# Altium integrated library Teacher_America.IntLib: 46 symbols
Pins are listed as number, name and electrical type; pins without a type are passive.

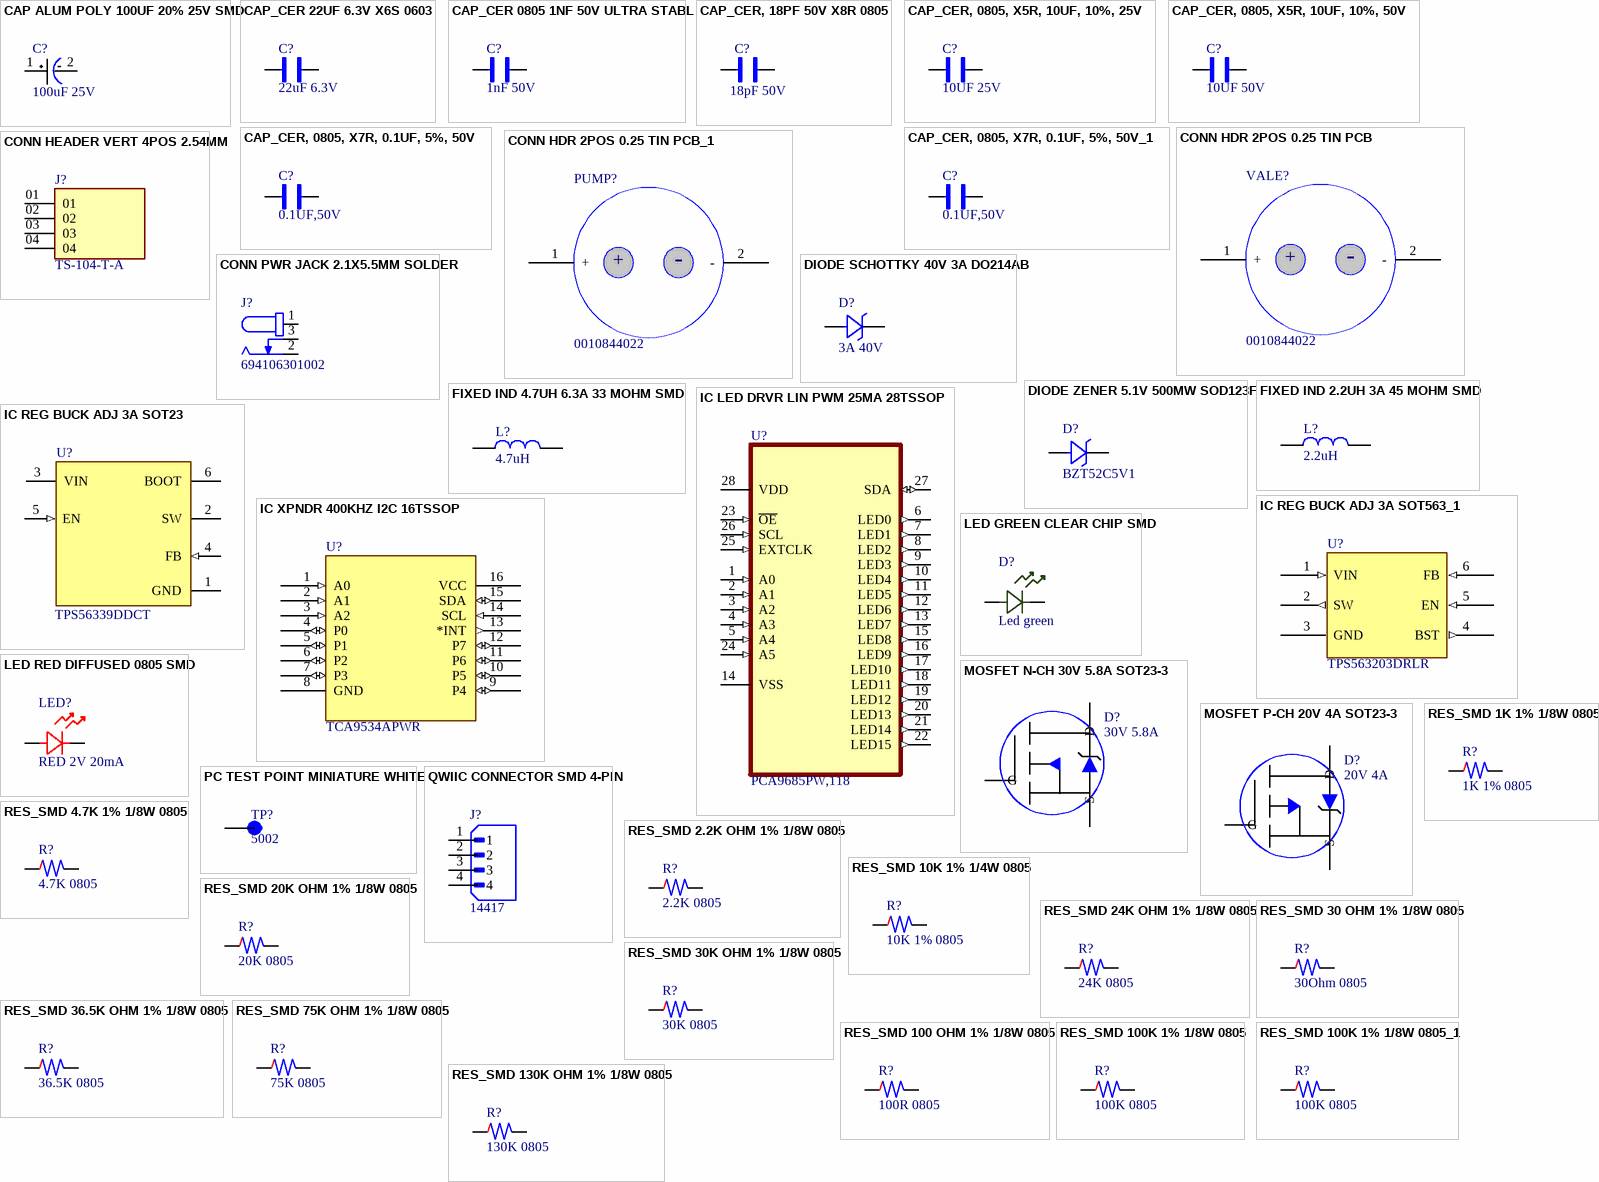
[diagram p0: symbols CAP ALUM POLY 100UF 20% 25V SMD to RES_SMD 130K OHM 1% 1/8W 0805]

## CAP ALUM POLY 100UF 20% 25V SMD
designator C?, comment 100uF 25V
WCAP-PSLC Aluminum Polymer Capacitors; Manufacturer: Wurth Elektronik; Manufacturer Part Number: 875075561005; Manufacturer Lifecycle Status: ACTIVE; Capacitance: 100µF; ESR (Equivalent Series Resistance): 15mΩ; Leakage Current: 500µA; Life (Hours): 2000hours; Pitch: 10.3mm; Polarity: Polar; Ripple Current: 4.8A; Tolerance: 20%; YEOL: 1 = Estimated lifetime > 10 years; LIB MADE BY: MR HOANG
footprint CAP_ALUM_SMD_D10_H12.4
pins: 1, 2

## CAP_CER 22UF 6.3V X6S 0603
designator C?, comment 22uF 6.3V
6.3V 22uF X6S ±20% 0603 Multilayer Ceramic Capacitors MLCC - SMD/SMT ROHS; Manufacturer: Murata; Manufacturer Part Number: GRM188C80J226ME15D; Manufacturer Lifecycle Status: IN PRODUCTION; Capacitance: 22µF; LIB MADE BY: MR HOANG
footprint CAP_CER_0603
pins: 1, 2

## CAP_CER 0805 1NF 50V ULTRA STABL
designator C?, comment 1nF 50V
Cap Ceramic 0.001uF 50V X8R 10% Pad SMD 0805 150C T/R Automotive AEC-Q200; Manufacturer: Yageo Group; Manufacturer Part Number: C0805C102K5HACAUTO; Temperature Coefficient: 30ppm/°C; LIB MADE BY: MR HOANG
footprint CAP_CER_0805
pins: 1, 2

## CAP_CER, 18PF 50V X8R 0805
designator C?, comment 18pF 50V
Multilayer Ceramic Capacitors MLCC - SMD/SMT 50V 18pF X8R 0805 5%; Manufacturer: Yageo Group; Manufacturer Part Number: C0805C180J5HACTU; Temperature Coefficient: 30ppm/°C; LIB MADE BY: MR HOANG
footprint CAP_CER_0805
pins: 1, 2

## CAP_CER, 0805, X5R, 10UF, 10%, 25V
designator C?, comment 10UF 25V
Cap SMD, 0805, X5R, 10UF, 10%, 25V; Manufacturer: Nextgen; Manufacturer Part Number: 0805W106K250CC; LIB MADE BY: MR HOANG
footprint CAP_CER_0805
pins: 1, 2

## CAP_CER, 0805, X5R, 10UF, 10%, 50V
designator C?, comment 10UF 50V
CAP_CER,0805,X5R,10UF,10%,50V; Manufacturer: Nextgen; Manufacturer Part Number: 0805W106K500CC; LIB MADE BY: MR HOANG
footprint CAP_CER_0805
pins: 1, 2

## CAP_CER, 0805, X7R, 0.1UF, 5%, 50V
designator C?, comment 0.1UF,50V
Ceramic Capacitor, Multilayer, Ceramic, 50V, 10% +Tol, 10% -Tol, X7R, 15% TC, 0.1uF, Surface Mount, 0805; Manufacturer: Nextgen; Manufacturer Part Number: 0805B104K500BD; Capacitance: 100nF; LIB MADE BY: MR HOANG
footprint CAP_CER_0805
pins: 1, 2

## CAP_CER, 0805, X7R, 0.1UF, 5%, 50V_1
designator C?, comment 0.1UF,50V
Ceramic Capacitor, Multilayer, Ceramic, 50V, 10% +Tol, 10% -Tol, X7R, 15% TC, 0.1uF, Surface Mount, 0805; Manufacturer: Nextgen; Manufacturer Part Number: 0805B104K500BD; Capacitance: 100nF; LIB MADE BY: MR HOANG
footprint CAP_CER_0805
pins: 1, 2

## CONN HDR 2POS 0.25 TIN PCB
designator VALE?, comment 0010844022
Connector Header 2 Position 6.35mm Solder Straight Thru-Hole 2 Terminal 1 Port MLX-Series; Manufacturer: Molex; Manufacturer Lifecycle Status: ACTIVE; Connector Type: Power; Contact Resistance: 3.5mΩ; Current Rating: 13.5A; Dielectric Material: Polyester; Gender: Female; Glow Wire Compliant: Non-compliant; Insulation Resistance: 1GΩ; Number of Circuits: 2; Operating Force: 6.672N; Plating: Tin; Plating Thickness: 3.5052µm; Ratings: CSA; Voltage Rating: 600V; LIB MADE BY: MR HOANG
footprint CONN_SDA_42002-xxxxx_02_MOL
pins: 1 +, 2 -

## CONN HDR 2POS 0.25 TIN PCB_1
designator PUMP?, comment 0010844022
Connector Header 2 Position 6.35mm Solder Straight Thru-Hole 2 Terminal 1 Port MLX-Series; Manufacturer: Molex; Manufacturer Lifecycle Status: ACTIVE; Connector Type: Power; Contact Resistance: 3.5mΩ; Current Rating: 13.5A; Dielectric Material: Polyester; Gender: Female; Glow Wire Compliant: Non-compliant; Insulation Resistance: 1GΩ; Number of Circuits: 2; Operating Force: 6.672N; Plating: Tin; Plating Thickness: 3.5052µm; Ratings: CSA; Voltage Rating: 600V; LIB MADE BY: MR HOANG
footprint CONN_SDA_42002-xxxxx_02_MOL
pins: 1 +, 2 -

## CONN HEADER VERT 4POS 2.54MM
designator J?, comment TS-104-T-A
Samtec 2.54mmpitch4pSingle row pin header, TSseries, right angle, Through hole mounting; Manufacturer Lifecycle Status: PRODUCTION; Gender: Male; Number of Contacts: 4; Pitch: 2.54mm; LIB MADE BY: MR HOANG
footprint HDR_THT_1x04_P2.54
pins: 01, 02, 03, 04

## CONN PWR JACK 2.1X5.5MM SOLDER
designator J?, comment 694106301002
DC Power Jack Connector WR-DC, Male, Right Angled, THT, 5 A, 24 V; Manufacturer: Wurth Elektronik; Manufacturer Lifecycle Status: ACTIVE; Current Rating: 5A; Insulation Resistance: 100MΩ; Number of Contacts: 3; Operating Supply Voltage: 24V; Shielding: Unshielded; YEOL: 1 = Estimated lifetime > 10 years; LIB MADE BY: MR HOANG
footprint CONN PWR JACK 2.1X5.5MM SOLDER
pins: 1, 2, 3

## DIODE SCHOTTKY 40V 3A DO214AB
designator D?, comment 3A 40V
Rectifier Diode, Schottky, 1 Phase, 1 Element, 3A, 40V V(RRM), Silicon, DO-214AB; Manufacturer: onsemi; Manufacturer Part Number: SS34; Manufacturer Lifecycle Status: ACTIVE; Element Configuration: Single; Forward Voltage: 500mV; Max Forward Surge Current (Ifsm): 100A; Max Junction Temperature (Tj): 150°C; Max Power Dissipation: 2.27W; Max Reverse Leakage Current: 500µA; Number of Elements: 1; Peak Reverse Current: 20mA; Polarity: Standard; LIB MADE BY: MR HOANG
footprint DO214AA
pins: 1 CATHODE, 2 ANODE

## DIODE ZENER 5.1V 500MW SOD123F
designator D?, comment BZT52C5V1
BZT52C5V1 Series 500 mW 5.1 V 10 mA Surface Mount Zener Diode - SOD-123; Manufacturer: Diodes Inc.; Manufacturer Part Number: BZT52C5V1-7-F; Current: 1A; Element Configuration: Single; Forward Current: 10mA; Forward Voltage: 900mV; Impedance: 60Ω; Max Junction Temperature (Tj): 150°C; Max Power Dissipation: 370mW; Max Reverse Leakage Current: 2µA; Number of Elements: 1; Output Current: 50mA; Polarity: Unidirectional; Power Rating: 500mW; Reference Voltage: 5.1V; Reverse Standoff Voltage: 2V; Test Current: 5mA; Tolerance: 6%; Voltage Tolerance: 5.88%; LIB MADE BY: MR HOANG
footprint SOD-123
pins: 1 CATHODE, 2 ANODE

## FIXED IND 2.2UH 3A 45 MOHM SMD
designator L?, comment 2.2uH
Inductor Power Shielded Wirewound 2.2uH 20% 100KHz Ferrite 3.1A 0.045Ohm DCR 1515 T/R; Manufacturer: Vishay; Manufacturer Part Number: IFSC1515AHER2R2M01; Current Rating: 3A; DC Resistance (DCR): 45mΩ; Inductance: 2.2µH; Max Current Rating: 2.8A; Number of Circuits: 1; Resistance: 35mΩ; LIB MADE BY: MR HOANG
footprint IND_12.5x12.5_H8.5
pins: 1, 2

## FIXED IND 4.7UH 6.3A 33 MOHM SMD
designator L?, comment 4.7uH
FIXED IND 4.7UH 6.3A 33MOHM SMD / 4.7 µH Shielded Molded Inductor 6.3 A 33mOhm Max Nonstandard; Manufacturer: Sumida; Manufacturer Part Number: 0630CDMCCDS-4R7MC; Core Material: Metal; DC Resistance (DCR): 33mΩ; Inductance: 4.7µH; Number of Circuits: 1; Saturation Current: 6.8A; Test Frequency: 100kHz; Tolerance: 20%
footprint IND_6.8X6.5_H2.8
pins: 1, 2

## IC LED DRVR LIN PWM 25MA 28TSSOP
designator U?, comment PCA9685PW,118
PCA9685 Series 5.5V 25 mA 1 MHz 12-bit PWM Fm+I2C-Bus LED Controller - TSSOP-28; Manufacturer: NXP Semiconductors; Frequency: 25MHz; High Level Output Current: 10mA; Low Level Output Current: 400A; Max Power Dissipation: 400mW; Min Supply Voltage: 2.3V; Nominal Supply Current: 6mA; Nominal Supply Voltage (DC): 3V; Number of Characters: 16; Number of Circuits: 1; Output Current: 25mA; Output Voltage: 5V; Power Dissipation: 400W; LIB MADE BY: MR HOANG
footprint TSSOP-28
pins: 1 A0 (in), 2 A1 (in), 3 A2 (in), 4 A3 (in), 5 A4 (in), 6 LED0 (out), 7 LED1 (out), 8 LED2 (out), 9 LED3 (out), 10 LED4 (out), 11 LED5 (out), 12 LED6 (out), 13 LED7 (out), 14 VSS, 15 LED8 (out), 16 LED9 (out), 17 LED10 (out), 18 LED11 (out), 19 LED12 (out), 20 LED13 (out), 21 LED14 (out), 22 LED15 (out), 23 ~{OE} (in), 24 A5 (in), 25 EXTCLK (in), 26 SCL (in), 27 SDA (io), 28 VDD (power)

## IC REG BUCK ADJ 3A SOT23
designator U?, comment TPS56339DDCT
4.5-V to 24-V input, 3-A output synchronous buck converter 6-SOT-23-THIN -40 to 125; Manufacturer: Texas Instruments; Manufacturer Lifecycle Status: ACTIVE; LIB MADE BY: MR HOANG
footprint SOT-23-6
pins: 1 GND (power), 2 SW (power), 3 VIN (power), 4 FB (in), 5 EN (in), 6 BOOT (power)

## IC REG BUCK ADJ 3A SOT563_1
designator U?, comment TPS563203DRLR
4.2-V to 17-V input, 3-A synchronous buck converter in SOT563 6-SOT-5X3 -40 to 125; Manufacturer: Texas Instruments; Manufacturer Lifecycle Status: ACTIVE; LIB MADE BY: MR HOANG
footprint SOT-563
pins: 1 VIN (in), 2 SW (out), 3 GND (power), 4 BST (out), 5 EN (in), 6 FB (in)

## IC XPNDR 400KHZ I2C 16TSSOP
designator U?, comment TCA9534APWR
I2C Level Shifter, 8-Bit, 1.65V-5.5V, 400kHz, TSSOP-16, SMD, Adhesive Mount, 1.2mm H; Manufacturer: Texas Instruments; Manufacturer Lifecycle Status: ACTIVE; Interface: I2C, SMBus; Max Junction Temperature (Tj): 100°C; Max Supply Voltage: 5.5V; Min Supply Voltage: 1.65V; Number of I/Os: 8; LIB MADE BY: MR HOANG
footprint 16-TSSOP
pins: 1 A0 (in), 2 A1 (in), 3 A2 (in), 4 P0 (io), 5 P1 (io), 6 P2 (io), 7 P3 (io), 8 GND (power), 9 P4 (io), 10 P5 (io), 11 P6 (io), 12 P7 (io), 13 *INT (out), 14 SCL (in), 15 SDA (io), 16 VCC (power)

## LED GREEN CLEAR CHIP SMD
designator D?, comment Led green
Single-color LEDs; LITEON; LTST-C190GKT; Green; 130 °; 2.1 V; 0603; Manufacturer: Diodes Inc.; Current: 1A; Dominant Wavelength: 569nm; Forward Current: 30mA; Forward Voltage: 2.6V; Lens Color: Clear, Colorless; Lens Style: Clear; Luminous Intensity: 1.8mcd; Number of Circuits: 1; Peak Wavelength: 565nm; Power Dissipation: 100mW; Reverse Voltage: 5V; Shape: Rectangular; Test Current: 10mA; Viewing Angle: 130°; Voltage: 2V; LIB MADE BY: MR HOANG
footprint LED_LS R976_AOS
pins: 1, 2

## LED RED DIFFUSED 0805 SMD
designator LED?, comment RED 2V 20mA
Red 633nm LED Indication - Discrete 2V 0805 (2012 Metric); Manufacturer: Osram; Manufacturer Part Number: LS R976-NR-1-0-20-R18; LIB MADE BY: MR HOANG
footprint LED_LS R976_AOS
pins: 1, 2

## MOSFET N-CH 30V 5.8A SOT23-3
designator D?, comment 30V 5.8A
Trans MOSFET N-CH 30V 5.7A 3-Pin SOT-23; Manufacturer: Alpha & Omega Semiconductor; Manufacturer Part Number: AO3400A; Drain to Source Resistance: 26.5mΩ; Gate to Source Voltage (Vgs): 12V; Input Capacitance: 630pF; Max Junction Temperature (Tj): 150°C; Max Power Dissipation: 1.4W; Number of Channels: 1; Threshold Voltage: 650mV; Turn-Off Delay Time: 25ns; Turn-On Delay Time: 3ns; LIB MADE BY: MR HOANG
footprint SOT-23-3
pins: 1 G, 2 S, 3 D

## MOSFET P-CH 20V 4A SOT23-3
designator D?, comment 20V 4A
P-ch Mosfet 20V 4A 39MΩ@4A, 4.5V 9.1NC@4.5V 294PF@10V SOT-23-3 SMD 2.9MM × 1.3MM × 1.03MM; Manufacturer: Diodes Inc.; Manufacturer Part Number: DMG3415U-7; Drain to Source Breakdown Voltage: -20V; Drain to Source Resistance: 42.5mΩ; Element Configuration: Single; Fall Time: 393ns; Gate to Source Voltage (Vgs): 8V; Input Capacitance: 294pF; Max Junction Temperature (Tj): 150°C; Max Power Dissipation: 900mW; Nominal Vgs: -550mV; Number of Channels: 1; Rds On Max: 39mΩ; Rise Time: 117ns; Turn-Off Delay Time: 795ns; Turn-On Delay Time: 71ns; LIB MADE BY: MR HOANG
footprint SOT-23-3
pins: 1 G, 2 S, 3 D

## PC TEST POINT MINIATURE WHITE
designator TP?, comment 5002
Test Point, Mini, Thm, Pc, .300 L, .100 Od, Heat Resistant Nylon 46, White; Manufacturer: Keystone; Body Material: Bronze, PBT; Hole Diameter: 1.6mm; Inside Diameter: 1.27mm; Insulation: Insulated; Number of Ports: 1; Outside Diameter: 2.54mm; Plating: Silver; LIB MADE BY: MR HOANG
footprint KEYSTONE_5002
pins: TP

## QWIIC CONNECTOR SMD 4-PIN
designator J?, comment 14417
Qwiic Connector SMD 4-PIN; Manufacturer: SparkFun; LIB MADE BY: MR HOANG
footprint SPARKFUN_PRT-14417
pins: 1, 2, 3, 4

## RES_SMD 1K 1% 1/8W 0805
designator R?, comment 1K 1% 0805
Yageo RC0805FR-071KL SMD Resistor 0603 1k Ohm ±1% Thick Film; Manufacturer: Yageo Group; Max Power Dissipation: 125mW; Resistance: 1kΩ; Temperature Coefficient: 100ppm/°C; Voltage Rating: 150V; LIBRARY MADE BY: Mr. HOANG
footprint RES_0805
pins: 1, 2

## RES_SMD 2.2K OHM 1% 1/8W 0805
designator R?, comment 2.2K 0805
125Mw Thick Film Resistors 100Ppm/ 1% 2.2K 0805 Chip Resistor Surface Mount Rohs; Manufacturer: Yageo Group; Manufacturer Part Number: RC0805FR-072K2L; Resistance: 2.2kΩ; Temperature Coefficient: 100ppm/°C; Voltage Rating: 150V; LIB MADE BY: MR HOANG
footprint RES_0805
pins: 1, 2

## RES_SMD 4.7K 1% 1/8W 0805
designator R?, comment 4.7K 0805
Res Thick Film 0805 4.7K Ohm 1% 0.125W(1/8W) ±100ppm/C Pad SMD T/R; Manufacturer: Vishay; Manufacturer Part Number: CRCW08054K70FKEAC; Power Dissipation: 125mW; Resistance: 4.7kΩ; Temperature Coefficient: 100ppm/°C; Voltage Rating: 150V; LIB MADE BY: MR HOANG
footprint RES_0805
pins: 1, 2

## RES_SMD 10K 1% 1/4W 0805
designator R?, comment 10K 1% 0805
Res Thick Film 0805 10K Ohm 1% 0.125W(1/8W) ±100ppm/C Pad SMD Automotive T/R; Manufacturer: Vishay; Manufacturer Part Number: CRCW080510K0FKEA; Manufacturer Package Identifier: CRCW0805-e3; Power Dissipation: 125mW; Power Rating: 120mW; Resistance: 10kΩ; Temperature Coefficient: 100ppm/°C; Voltage Rating: 150V; LIB MADE BY: MR HOANG
footprint RES_0805
pins: 1, 2

## RES_SMD 20K OHM 1% 1/8W 0805
designator R?, comment 20K 0805
Res Thick Film 0805 20K Ohm 1% 1/8W ±100ppm/°C Molded SMD Punched Carrier T/R; Manufacturer: Panasonic; Manufacturer Part Number: ERJ6ENF2002V; Manufacturer Lifecycle Status: ACTIVE; Part Series: Precision Thick Film Chip Resistors; Max Power Dissipation: 125mW; Resistance: 20kΩ; Voltage Rating: 150V; LIB MADE BY: MR HOANG
footprint RES_0805
pins: 1, 2

## RES_SMD 24K OHM 1% 1/8W 0805
designator R?, comment 24K 0805
Res Thick Film 0805 24K Ohm 1% 0.125W(1/8W) ±100ppm/C Pad SMD T/R; Manufacturer: Yageo Group; Manufacturer Part Number: RC0805FR-0724KL; Manufacturer Package Identifier: 0805 (2012 metric); Power Rating: 125mW; Resistance: 24kΩ; Temperature Coefficient: 100ppm/°C; Voltage Rating: 150V; LIB MADE BY: MR HOANG
footprint RES_0805
pins: 1, 2

## RES_SMD 30 OHM 1% 1/8W 0805
designator R?, comment 30Ohm 0805
Res Thick Film 0805 30 Ohm 1% 0.125W(1/8W) ±100ppm/C Pad SMD T/R; Manufacturer: Yageo Group; Manufacturer Part Number: RC0805FR-0730RL; Manufacturer Package Identifier: 0805 (2012 metric); Max Power Dissipation: 125mW; Resistance: 30Ω; Temperature Coefficient: 100ppm/°C; Voltage Rating: 150V; LIB MADE BY: MR HOANG
footprint RES_0805
pins: 1, 2

## RES_SMD 30K OHM 1% 1/8W 0805
designator R?, comment 30K 0805
Res Thick Film 0805 30K Ohm 1% 0.125W ±100ppm/°C Molded SMD Paper T/R; Manufacturer: Stackpole Electronics; Manufacturer Part Number: RMCF0805FT30K0; Manufacturer Package Identifier: 0805 (2012 metric); Max Power Dissipation: 125mW; Resistance: 30kΩ; Voltage Rating: 150V; LIB MADE BY: MR HOANG
footprint RES_0805
pins: 1, 2

## RES_SMD 36.5K OHM 1% 1/8W 0805
designator R?, comment 36.5K 0805
Res Thick Film 0805 36.5K Ohm 1% 0.125W ±100ppm/°C Molded SMD Paper T/R; Manufacturer: Stackpole Electronics; Manufacturer Part Number: RMCF0805FT36K5; Manufacturer Package Identifier: 0805 (2012 metric); Max Power Dissipation: 125mW; Resistance: 36.5kΩ; Voltage Rating: 150V; LIB MADE BY: MR HOANG
footprint RES_0805
pins: 1, 2

## RES_SMD 75K OHM 1% 1/8W 0805
designator R?, comment 75K 0805
Res Thick Film 0805 75K Ohm 1% 1/8W ±100ppm/°C Molded SMD SMD Paper Tape on Plastic Reel; Manufacturer: Bourns; Manufacturer Part Number: CR0805-FX-7502ELF; Power Rating: 125mW; Resistance: 75kΩ; Voltage Rating: 150V; LIB MADE BY: MR HOANG
footprint RES_0805
pins: 1, 2

## RES_SMD 100 OHM 1% 1/8W 0805
designator R?, comment 100R 0805
Resistor Thick Film 0805 100 Ohm 1% 1/8W 100ppm/C Molded SMD Punched Carrier T/R; Manufacturer: Panasonic; Manufacturer Part Number: ERJ6ENF1000V; Manufacturer Lifecycle Status: ACTIVE; Manufacturer Package Identifier: 0805 (2012 metric); Part Series: Precision Thick Film Chip Resistors; Max Power Dissipation: 125mW; Resistance: 100Ω; Temperature Coefficient: 100ppm/°C; Voltage Rating: 150V; LIB MADE BY: MR HOANG
footprint RES_0805
pins: 1, 2

## RES_SMD 100K 1% 1/8W 0805
designator R?, comment 100K 0805
125mW Thick Film Resistors 150V ±100ppm/℃ ±1% 100kΩ 0805 Chip Resistor - Surface Mount ROHS; Manufacturer: Yageo Group; Manufacturer Part Number: RC0805FR-07100KL; Temperature Coefficient: 100ppm/°C; LIB MADE BY: MR HOANG
footprint RES_0805
pins: 1, 2

## RES_SMD 100K 1% 1/8W 0805_1
designator R?, comment 100K 0805
125mW Thick Film Resistors 150V ±100ppm/℃ ±1% 100kΩ 0805 Chip Resistor - Surface Mount ROHS; Manufacturer: Yageo Group; Manufacturer Part Number: RC0805FR-07100KL; Temperature Coefficient: 100ppm/°C; LIB MADE BY: MR HOANG
footprint RES_0805
pins: 1, 2

## RES_SMD 130K OHM 1% 1/8W 0805
designator R?, comment 130K 0805
Res Thick Film 0805 130K Ohm 1% 0.125W(1/8W) ±100ppm/C Pad SMD T/R; Manufacturer: Yageo Group; Manufacturer Part Number: RC0805FR-07130KL; Max Power Dissipation: 125mW; Resistance: 130kΩ; Temperature Coefficient: 100ppm/°C; Voltage Rating: 150V; LIB MADE BY: MR HOANG
footprint RES_0805
pins: 1, 2

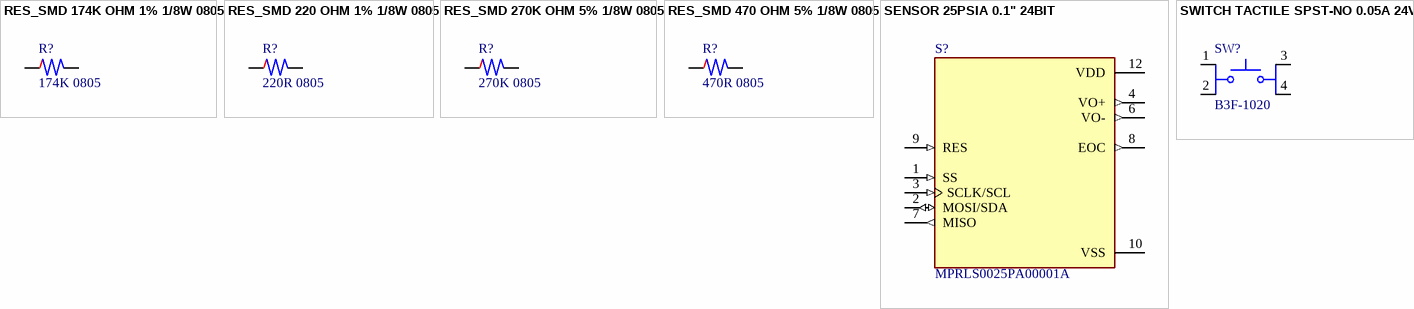
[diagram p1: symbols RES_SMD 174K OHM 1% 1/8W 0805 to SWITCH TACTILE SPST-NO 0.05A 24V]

## RES_SMD 174K OHM 1% 1/8W 0805
designator R?, comment 174K 0805
Res Thick Film 0805 174K Ohm 1% 0.125W(1/8W) ±100ppm/C Pad SMD T/R Automotive AEC-Q200; Manufacturer: Vishay; Manufacturer Part Number: CRCW0805174KFKEA; Manufacturer Package Identifier: CRCW0805-e3; Max Power Dissipation: 125mW; Resistance: 174kΩ; Temperature Coefficient: 100ppm/°C; Voltage Rating: 150V; LIB MADE BY: MR HOANG
footprint RES_0805
pins: 1, 2

## RES_SMD 220 OHM 1% 1/8W 0805
designator R?, comment 220R 0805
Res Thick Film 0805 220 Ohm 1% 0.125W(1/8W) ±100ppm/C Pad SMD Automotive T/R; Manufacturer: TE Connectivity; Manufacturer Part Number: CRGCQ0805F220R; Manufacturer Lifecycle Status: ACTIVE; Operating Supply Voltage: 150V; Power Rating: 125mW; Resistance: 220Ω; Temperature Coefficient: 100ppm/°C; LIB MADE BY: MR HOANG
footprint RES_0805
pins: 1, 2

## RES_SMD 270K OHM 5% 1/8W 0805
designator R?, comment 270K 0805
Res Thick Film 0805 270K Ohm 5% 0.125W(1/8W) ±100ppm/C Pad SMD T/R; Manufacturer: Yageo Group; Manufacturer Part Number: RC0805JR-07270KL; Manufacturer Package Identifier: 0805 (2012 metric); Max Power Dissipation: 125mW; Resistance: 270kΩ; Temperature Coefficient: 100ppm/°C; Voltage Rating: 150V; LIB MADE BY: MR HOANG
footprint RES_0805
pins: 1, 2

## RES_SMD 470 OHM 5% 1/8W 0805
designator R?, comment 470R 0805
Res Thick Film 0805 470 Ohm 5% 0.125W(1/8W) ±100ppm/C Pad SMD T/R Automotive AEC-Q200; Manufacturer: TE Connectivity; Manufacturer Part Number: CRGCQ0805J470R; Manufacturer Lifecycle Status: ACTIVE; Operating Supply Voltage: 150V; Power Rating: 125mW; Resistance: 470Ω; Temperature Coefficient: 100ppm/°C
footprint RES_0805
pins: 1, 2

## SENSOR 25PSIA 0.1" 24BIT
designator S?, comment MPRLS0025PA00001A
Board Mount Pressure Sensor -0.3V to 3.9V 0psi to 25psi Absolute 12-Pin T/R; Manufacturer: Honeywell; Accuracy: 0.25%; Current Rating: 1.7mA; Max Supply Voltage: 3.6V; Min Supply Voltage: 1.8V; Number of Bits: 14; Operating Supply Current: 33.8µA; Port Style: Barbless; LIB MADE BY: MR HOANG
footprint XDCR_MPRLS0025PA00001A
pins: 1 SS (in), 2 MOSI/SDA (io), 3 SCLK/SCL (in), 4 VO+ (out), 6 VO- (out), 7 MISO (out), 8 EOC (out), 9 RES (in), 10 VSS (power), 12 VDD (power)

## SWITCH TACTILE SPST-NO 0.05A 24V
designator SW?, comment B3F-1020
Switch Tactile N.O. SPST Flat Round Button PC Pins 0.05A 24VDC 0.98N Thru-Hole Bag; Manufacturer: Omron; Actuator Length: 900µm; Contact Current Rating: 50mA; Contact Resistance: 100mΩ; Electrical Life: 1Mcycles; Illumination Type: Illuminated, Non-Illuminated; Max Voltage Rating (DC): 24V; Number of Poles: 1; Operating Force: 1.27N; Switch Function: Off-Mom; Switch Travel: 250µm; LIB MADE BY: MR HOANG
footprint SW_B3F-1000_OMR
pins: 1, 2, 3, 4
